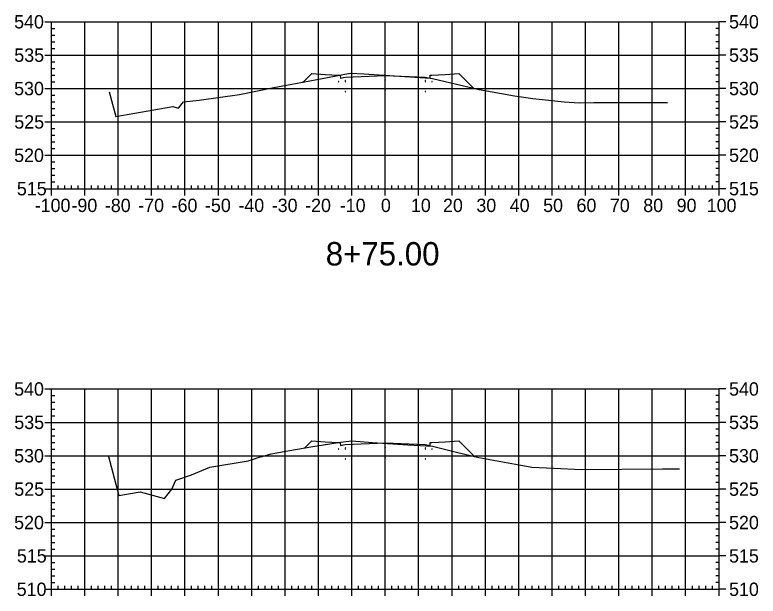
# Model space of a CAD drawing. Extents: x 708103 to 717568, y 374476 to 378707.
# Drawn here: x 716520.5 to 716743.2, y 376546 to 376720.1 of the extents above; entities that cross this region are included whole.
import ezdxf

# ---------------------------------------------------------------- set-up
doc = ezdxf.new("R2010")
doc.units = 0
for name, color, linetype in [('1', 7, 'Continuous'), ('14', 7, 'Continuous'), ('22', 7, 'Continuous'), ('57', 7, 'Continuous'), ('Existing', 7, 'Continuous')]:
    doc.layers.add(name, color=color, linetype=linetype)

msp = doc.modelspace()

# ---------------------------------------------------------------- linework, layer by layer
for points in [[(716617.45, 376700.07), (716617.55, 376700.07), (716617.55, 376700.17), (716617.45, 376700.17)], [(716619.45, 376700.4), (716619.55, 376700.4), (716619.55, 376700.5), (716619.45, 376700.5)], [(716619.45, 376700.07), (716619.55, 376700.07), (716619.55, 376700.17), (716619.45, 376700.17)], [(716631.45, 376700.55), (716631.55, 376700.55), (716631.55, 376700.65), (716631.45, 376700.65)], [(716643.45, 376700.4), (716643.55, 376700.4), (716643.55, 376700.5), (716643.45, 376700.5)], [(716643.45, 376700.07), (716643.55, 376700.07), (716643.55, 376700.17), (716643.45, 376700.17)], [(716645.45, 376700.07), (716645.55, 376700.07), (716645.55, 376700.17), (716645.45, 376700.17)], [(716619.45, 376697.07), (716619.55, 376697.07), (716619.55, 376697.17), (716619.45, 376697.17)], [(716631.45, 376697.55), (716631.55, 376697.55), (716631.55, 376697.65), (716631.45, 376697.65)], [(716643.45, 376697.07), (716643.55, 376697.07), (716643.55, 376697.17), (716643.45, 376697.17)], [(716617.45, 376590.02), (716617.55, 376590.02), (716617.55, 376590.12), (716617.45, 376590.12)], [(716619.45, 376590.36), (716619.55, 376590.36), (716619.55, 376590.46), (716619.45, 376590.46)], [(716619.45, 376590.02), (716619.55, 376590.02), (716619.55, 376590.12), (716619.45, 376590.12)], [(716631.45, 376590.5), (716631.55, 376590.5), (716631.55, 376590.6), (716631.45, 376590.6)], [(716643.45, 376590.36), (716643.55, 376590.36), (716643.55, 376590.46), (716643.45, 376590.46)], [(716643.45, 376590.02), (716643.55, 376590.02), (716643.55, 376590.12), (716643.45, 376590.12)], [(716645.45, 376590.02), (716645.55, 376590.02), (716645.55, 376590.12), (716645.45, 376590.12)], [(716631.45, 376587.5), (716631.55, 376587.5), (716631.55, 376587.6), (716631.45, 376587.6)], [(716619.45, 376587.02), (716619.55, 376587.02), (716619.55, 376587.12), (716619.45, 376587.12)], [(716643.45, 376587.02), (716643.55, 376587.02), (716643.55, 376587.12), (716643.45, 376587.12)]]:
    msp.add_lwpolyline(points, close=True)
at = {"layer": '14'}
for points in [[(716606.91, 376700.01), (716606.91, 376700.06), (716606.91, 376700.01), (716606.86, 376700.01), (716606.91, 376700.01), (716606.91, 376699.96), (716606.91, 376700.01), (716606.96, 376700.01)], [(716657.93, 376698.16), (716657.93, 376698.21), (716657.93, 376698.16), (716657.88, 376698.16), (716657.93, 376698.16), (716657.93, 376698.11), (716657.93, 376698.16), (716657.98, 376698.16)], [(716607.37, 376590.42), (716607.37, 376590.47), (716607.37, 376590.42), (716607.32, 376590.42), (716607.37, 376590.42), (716607.37, 376590.37), (716607.37, 376590.42), (716607.42, 376590.42)], [(716658.21, 376587.84), (716658.21, 376587.89), (716658.21, 376587.84), (716658.16, 376587.84), (716658.21, 376587.84), (716658.21, 376587.79), (716658.21, 376587.84), (716658.26, 376587.84)]]:
    msp.add_lwpolyline(points, dxfattribs=at)
at = {"layer": '22'}
for points in [[(716606.91, 376700.01), (716609.5, 376702.6), (716613.5, 376702.28), (716617.5, 376702.12), (716618, 376702.12), (716618.08, 376701.2), (716619.5, 376701.45), (716631.5, 376701.93), (716643.5, 376701.45), (716644.91, 376701.2), (716645, 376702.12), (716645.5, 376702.12), (716649.5, 376702.28), (716653.5, 376702.6), (716657.93, 376698.16)], [(716607.37, 376590.42), (716609.5, 376592.55), (716613.5, 376592.23), (716617.5, 376592.07), (716618, 376592.07), (716618.08, 376591.16), (716619.5, 376591.41), (716631.5, 376591.89), (716643.5, 376591.41), (716644.91, 376591.16), (716645, 376592.07), (716645.5, 376592.07), (716649.5, 376592.23), (716653.5, 376592.55), (716658.21, 376587.84)]]:
    msp.add_lwpolyline(points, dxfattribs=at)
at = {"layer": '57'}
for p, q in [((716529.5, 376718.07), (716531.5, 376718.07)), ((716531.5, 376718.07), (716731.5, 376718.07)), ((716531.5, 376668.07), (716531.5, 376718.07)), ((716531.5, 376668.07), (716531.5, 376718.07)), ((716541.5, 376668.07), (716541.5, 376718.07)), ((716551.5, 376668.07), (716551.5, 376718.07)), ((716561.5, 376668.07), (716561.5, 376718.07)), ((716571.5, 376668.07), (716571.5, 376718.07)), ((716581.5, 376668.07), (716581.5, 376718.07)), ((716591.5, 376668.07), (716591.5, 376718.07)), ((716601.5, 376668.07), (716601.5, 376718.07)), ((716611.5, 376668.07), (716611.5, 376718.07)), ((716621.5, 376668.07), (716621.5, 376718.07)), ((716631.5, 376668.07), (716631.5, 376718.07)), ((716641.5, 376668.07), (716641.5, 376718.07)), ((716651.5, 376668.07), (716651.5, 376718.07)), ((716661.5, 376668.07), (716661.5, 376718.07)), ((716671.5, 376668.07), (716671.5, 376718.07)), ((716681.5, 376668.07), (716681.5, 376718.07)), ((716691.5, 376668.07), (716691.5, 376718.07)), ((716701.5, 376668.07), (716701.5, 376718.07)), ((716711.5, 376668.07), (716711.5, 376718.07)), ((716721.5, 376668.07), (716721.5, 376718.07)), ((716731.5, 376668.07), (716731.5, 376718.07)), ((716731.5, 376668.07), (716731.5, 376718.07)), ((716733.5, 376718.07), (716731.5, 376718.07)), ((716531.5, 376716.07), (716532.5, 376716.07)), ((716731.5, 376716.07), (716730.5, 376716.07)), ((716531.5, 376714.07), (716532.5, 376714.07)), ((716731.5, 376714.07), (716730.5, 376714.07)), ((716531.5, 376712.07), (716532.5, 376712.07)), ((716531.5, 376710.07), (716532.5, 376710.07)), ((716731.5, 376712.07), (716730.5, 376712.07)), ((716731.5, 376710.07), (716730.5, 376710.07)), ((716529.5, 376708.07), (716531.5, 376708.07)), ((716531.5, 376708.07), (716731.5, 376708.07)), ((716733.5, 376708.07), (716731.5, 376708.07)), ((716531.5, 376706.07), (716532.5, 376706.07)), ((716731.5, 376706.07), (716730.5, 376706.07)), ((716531.5, 376704.07), (716532.5, 376704.07)), ((716731.5, 376704.07), (716730.5, 376704.07)), ((716531.5, 376702.07), (716532.5, 376702.07)), ((716731.5, 376702.07), (716730.5, 376702.07)), ((716531.5, 376700.07), (716532.5, 376700.07)), ((716731.5, 376700.07), (716730.5, 376700.07)), ((716529.5, 376698.07), (716531.5, 376698.07)), ((716531.5, 376698.07), (716731.5, 376698.07)), ((716733.5, 376698.07), (716731.5, 376698.07)), ((716531.5, 376696.07), (716532.5, 376696.07)), ((716731.5, 376696.07), (716730.5, 376696.07)), ((716531.5, 376694.07), (716532.5, 376694.07)), ((716731.5, 376694.07), (716730.5, 376694.07)), ((716531.5, 376692.07), (716532.5, 376692.07)), ((716531.5, 376690.07), (716532.5, 376690.07)), ((716731.5, 376692.07), (716730.5, 376692.07)), ((716731.5, 376690.07), (716730.5, 376690.07)), ((716529.5, 376688.07), (716531.5, 376688.07)), ((716531.5, 376688.07), (716731.5, 376688.07)), ((716733.5, 376688.07), (716731.5, 376688.07)), ((716531.5, 376686.07), (716532.5, 376686.07)), ((716731.5, 376686.07), (716730.5, 376686.07)), ((716531.5, 376684.07), (716532.5, 376684.07)), ((716731.5, 376684.07), (716730.5, 376684.07)), ((716531.5, 376682.07), (716532.5, 376682.07)), ((716731.5, 376682.07), (716730.5, 376682.07)), ((716531.5, 376680.07), (716532.5, 376680.07)), ((716731.5, 376680.07), (716730.5, 376680.07)), ((716529.5, 376678.07), (716531.5, 376678.07)), ((716531.5, 376678.07), (716731.5, 376678.07)), ((716733.5, 376678.07), (716731.5, 376678.07)), ((716531.5, 376676.07), (716532.5, 376676.07)), ((716731.5, 376676.07), (716730.5, 376676.07)), ((716531.5, 376674.07), (716532.5, 376674.07)), ((716731.5, 376674.07), (716730.5, 376674.07)), ((716531.5, 376672.07), (716532.5, 376672.07)), ((716531.5, 376670.07), (716532.5, 376670.07)), ((716731.5, 376672.07), (716730.5, 376672.07)), ((716731.5, 376670.07), (716730.5, 376670.07)), ((716529.5, 376668.07), (716531.5, 376668.07)), ((716531.5, 376668.07), (716731.5, 376668.07)), ((716531.5, 376668.07), (716731.5, 376668.07)), ((716531.5, 376666.07), (716531.5, 376668.07)), ((716533.5, 376668.07), (716533.5, 376669.07)), ((716535.5, 376668.07), (716535.5, 376669.07)), ((716537.5, 376668.07), (716537.5, 376669.07)), ((716539.5, 376668.07), (716539.5, 376669.07)), ((716541.5, 376666.07), (716541.5, 376668.07)), ((716543.5, 376668.07), (716543.5, 376669.07)), ((716545.5, 376668.07), (716545.5, 376669.07)), ((716547.5, 376668.07), (716547.5, 376669.07)), ((716549.5, 376668.07), (716549.5, 376669.07)), ((716551.5, 376666.07), (716551.5, 376668.07)), ((716553.5, 376668.07), (716553.5, 376669.07)), ((716555.5, 376668.07), (716555.5, 376669.07)), ((716557.5, 376668.07), (716557.5, 376669.07)), ((716559.5, 376668.07), (716559.5, 376669.07)), ((716561.5, 376666.07), (716561.5, 376668.07)), ((716563.5, 376668.07), (716563.5, 376669.07)), ((716565.5, 376668.07), (716565.5, 376669.07)), ((716567.5, 376668.07), (716567.5, 376669.07)), ((716569.5, 376668.07), (716569.5, 376669.07)), ((716571.5, 376666.07), (716571.5, 376668.07)), ((716573.5, 376668.07), (716573.5, 376669.07)), ((716575.5, 376668.07), (716575.5, 376669.07)), ((716577.5, 376668.07), (716577.5, 376669.07)), ((716579.5, 376668.07), (716579.5, 376669.07)), ((716581.5, 376666.07), (716581.5, 376668.07)), ((716583.5, 376668.07), (716583.5, 376669.07)), ((716585.5, 376668.07), (716585.5, 376669.07)), ((716587.5, 376668.07), (716587.5, 376669.07)), ((716589.5, 376668.07), (716589.5, 376669.07)), ((716591.5, 376666.07), (716591.5, 376668.07)), ((716593.5, 376668.07), (716593.5, 376669.07)), ((716595.5, 376668.07), (716595.5, 376669.07)), ((716597.5, 376668.07), (716597.5, 376669.07)), ((716599.5, 376668.07), (716599.5, 376669.07)), ((716601.5, 376666.07), (716601.5, 376668.07)), ((716603.5, 376668.07), (716603.5, 376669.07)), ((716605.5, 376668.07), (716605.5, 376669.07)), ((716607.5, 376668.07), (716607.5, 376669.07)), ((716609.5, 376668.07), (716609.5, 376669.07)), ((716611.5, 376666.07), (716611.5, 376668.07)), ((716613.5, 376668.07), (716613.5, 376669.07)), ((716615.5, 376668.07), (716615.5, 376669.07)), ((716617.5, 376668.07), (716617.5, 376669.07)), ((716619.5, 376668.07), (716619.5, 376669.07)), ((716621.5, 376666.07), (716621.5, 376668.07)), ((716623.5, 376668.07), (716623.5, 376669.07)), ((716625.5, 376668.07), (716625.5, 376669.07)), ((716627.5, 376668.07), (716627.5, 376669.07)), ((716629.5, 376668.07), (716629.5, 376669.07)), ((716631.5, 376666.07), (716631.5, 376668.07)), ((716633.5, 376668.07), (716633.5, 376669.07)), ((716635.5, 376668.07), (716635.5, 376669.07)), ((716637.5, 376668.07), (716637.5, 376669.07)), ((716639.5, 376668.07), (716639.5, 376669.07)), ((716641.5, 376666.07), (716641.5, 376668.07)), ((716643.5, 376668.07), (716643.5, 376669.07)), ((716645.5, 376668.07), (716645.5, 376669.07)), ((716647.5, 376668.07), (716647.5, 376669.07)), ((716649.5, 376668.07), (716649.5, 376669.07)), ((716651.5, 376666.07), (716651.5, 376668.07)), ((716653.5, 376668.07), (716653.5, 376669.07)), ((716655.5, 376668.07), (716655.5, 376669.07)), ((716657.5, 376668.07), (716657.5, 376669.07)), ((716659.5, 376668.07), (716659.5, 376669.07)), ((716661.5, 376666.07), (716661.5, 376668.07)), ((716663.5, 376668.07), (716663.5, 376669.07)), ((716665.5, 376668.07), (716665.5, 376669.07)), ((716667.5, 376668.07), (716667.5, 376669.07)), ((716669.5, 376668.07), (716669.5, 376669.07)), ((716671.5, 376666.07), (716671.5, 376668.07)), ((716673.5, 376668.07), (716673.5, 376669.07)), ((716675.5, 376668.07), (716675.5, 376669.07)), ((716677.5, 376668.07), (716677.5, 376669.07)), ((716679.5, 376668.07), (716679.5, 376669.07)), ((716681.5, 376666.07), (716681.5, 376668.07)), ((716683.5, 376668.07), (716683.5, 376669.07)), ((716685.5, 376668.07), (716685.5, 376669.07)), ((716687.5, 376668.07), (716687.5, 376669.07)), ((716689.5, 376668.07), (716689.5, 376669.07)), ((716691.5, 376666.07), (716691.5, 376668.07)), ((716693.5, 376668.07), (716693.5, 376669.07)), ((716695.5, 376668.07), (716695.5, 376669.07)), ((716697.5, 376668.07), (716697.5, 376669.07)), ((716699.5, 376668.07), (716699.5, 376669.07)), ((716701.5, 376666.07), (716701.5, 376668.07)), ((716703.5, 376668.07), (716703.5, 376669.07)), ((716705.5, 376668.07), (716705.5, 376669.07)), ((716707.5, 376668.07), (716707.5, 376669.07)), ((716709.5, 376668.07), (716709.5, 376669.07)), ((716711.5, 376666.07), (716711.5, 376668.07)), ((716713.5, 376668.07), (716713.5, 376669.07)), ((716715.5, 376668.07), (716715.5, 376669.07)), ((716717.5, 376668.07), (716717.5, 376669.07)), ((716719.5, 376668.07), (716719.5, 376669.07)), ((716721.5, 376666.07), (716721.5, 376668.07)), ((716723.5, 376668.07), (716723.5, 376669.07)), ((716725.5, 376668.07), (716725.5, 376669.07)), ((716727.5, 376668.07), (716727.5, 376669.07)), ((716729.5, 376668.07), (716729.5, 376669.07)), ((716731.5, 376666.07), (716731.5, 376668.07)), ((716733.5, 376668.07), (716731.5, 376668.07)), ((716529.5, 376608.07), (716531.5, 376608.07)), ((716531.5, 376608.07), (716731.5, 376608.07)), ((716531.5, 376548.07), (716531.5, 376608.07)), ((716531.5, 376548.07), (716531.5, 376608.07)), ((716541.5, 376548.07), (716541.5, 376608.07)), ((716551.5, 376548.07), (716551.5, 376608.07)), ((716561.5, 376548.07), (716561.5, 376608.07)), ((716571.5, 376548.07), (716571.5, 376608.07)), ((716581.5, 376548.07), (716581.5, 376608.07)), ((716591.5, 376548.07), (716591.5, 376608.07)), ((716601.5, 376548.07), (716601.5, 376608.07)), ((716611.5, 376548.07), (716611.5, 376608.07)), ((716621.5, 376548.07), (716621.5, 376608.07)), ((716631.5, 376548.07), (716631.5, 376608.07)), ((716641.5, 376548.07), (716641.5, 376608.07)), ((716651.5, 376548.07), (716651.5, 376608.07)), ((716661.5, 376548.07), (716661.5, 376608.07)), ((716671.5, 376548.07), (716671.5, 376608.07)), ((716681.5, 376548.07), (716681.5, 376608.07)), ((716691.5, 376548.07), (716691.5, 376608.07)), ((716701.5, 376548.07), (716701.5, 376608.07)), ((716711.5, 376548.07), (716711.5, 376608.07)), ((716721.5, 376548.07), (716721.5, 376608.07)), ((716731.5, 376548.07), (716731.5, 376608.07)), ((716731.5, 376548.07), (716731.5, 376608.07)), ((716733.5, 376608.07), (716731.5, 376608.07)), ((716531.5, 376606.07), (716532.5, 376606.07)), ((716731.5, 376606.07), (716730.5, 376606.07)), ((716531.5, 376604.07), (716532.5, 376604.07)), ((716731.5, 376604.07), (716730.5, 376604.07)), ((716531.5, 376602.07), (716532.5, 376602.07)), ((716731.5, 376602.07), (716730.5, 376602.07)), ((716531.5, 376600.07), (716532.5, 376600.07)), ((716731.5, 376600.07), (716730.5, 376600.07)), ((716529.5, 376598.07), (716531.5, 376598.07)), ((716531.5, 376598.07), (716731.5, 376598.07)), ((716733.5, 376598.07), (716731.5, 376598.07)), ((716531.5, 376596.07), (716532.5, 376596.07)), ((716731.5, 376596.07), (716730.5, 376596.07)), ((716531.5, 376594.07), (716532.5, 376594.07)), ((716531.5, 376592.07), (716532.5, 376592.07)), ((716731.5, 376594.07), (716730.5, 376594.07)), ((716731.5, 376592.07), (716730.5, 376592.07)), ((716531.5, 376590.07), (716532.5, 376590.07)), ((716731.5, 376590.07), (716730.5, 376590.07)), ((716529.5, 376588.07), (716531.5, 376588.07)), ((716531.5, 376588.07), (716731.5, 376588.07)), ((716733.5, 376588.07), (716731.5, 376588.07)), ((716531.5, 376586.07), (716532.5, 376586.07)), ((716731.5, 376586.07), (716730.5, 376586.07)), ((716531.5, 376584.07), (716532.5, 376584.07)), ((716731.5, 376584.07), (716730.5, 376584.07)), ((716531.5, 376582.07), (716532.5, 376582.07)), ((716731.5, 376582.07), (716730.5, 376582.07)), ((716531.5, 376580.07), (716532.5, 376580.07)), ((716731.5, 376580.07), (716730.5, 376580.07)), ((716529.5, 376578.07), (716531.5, 376578.07)), ((716531.5, 376578.07), (716731.5, 376578.07)), ((716733.5, 376578.07), (716731.5, 376578.07)), ((716531.5, 376576.07), (716532.5, 376576.07)), ((716731.5, 376576.07), (716730.5, 376576.07)), ((716531.5, 376574.07), (716532.5, 376574.07)), ((716531.5, 376572.07), (716532.5, 376572.07)), ((716731.5, 376574.07), (716730.5, 376574.07)), ((716731.5, 376572.07), (716730.5, 376572.07)), ((716531.5, 376570.07), (716532.5, 376570.07)), ((716731.5, 376570.07), (716730.5, 376570.07)), ((716529.5, 376568.07), (716531.5, 376568.07)), ((716531.5, 376568.07), (716731.5, 376568.07)), ((716733.5, 376568.07), (716731.5, 376568.07)), ((716531.5, 376566.07), (716532.5, 376566.07)), ((716731.5, 376566.07), (716730.5, 376566.07)), ((716531.5, 376564.07), (716532.5, 376564.07)), ((716731.5, 376564.07), (716730.5, 376564.07)), ((716531.5, 376562.07), (716532.5, 376562.07)), ((716731.5, 376562.07), (716730.5, 376562.07)), ((716531.5, 376560.07), (716532.5, 376560.07)), ((716731.5, 376560.07), (716730.5, 376560.07)), ((716529.5, 376558.07), (716531.5, 376558.07)), ((716531.5, 376558.07), (716731.5, 376558.07)), ((716733.5, 376558.07), (716731.5, 376558.07)), ((716531.5, 376556.07), (716532.5, 376556.07)), ((716731.5, 376556.07), (716730.5, 376556.07)), ((716531.5, 376554.07), (716532.5, 376554.07)), ((716531.5, 376552.07), (716532.5, 376552.07)), ((716731.5, 376554.07), (716730.5, 376554.07)), ((716731.5, 376552.07), (716730.5, 376552.07)), ((716531.5, 376550.07), (716532.5, 376550.07)), ((716731.5, 376550.07), (716730.5, 376550.07)), ((716529.5, 376548.07), (716531.5, 376548.07)), ((716531.5, 376548.07), (716731.5, 376548.07)), ((716531.5, 376548.07), (716731.5, 376548.07)), ((716531.5, 376546.07), (716531.5, 376548.07)), ((716533.5, 376548.07), (716533.5, 376549.07)), ((716535.5, 376548.07), (716535.5, 376549.07)), ((716537.5, 376548.07), (716537.5, 376549.07)), ((716539.5, 376548.07), (716539.5, 376549.07)), ((716541.5, 376546.07), (716541.5, 376548.07)), ((716543.5, 376548.07), (716543.5, 376549.07)), ((716545.5, 376548.07), (716545.5, 376549.07)), ((716547.5, 376548.07), (716547.5, 376549.07)), ((716549.5, 376548.07), (716549.5, 376549.07)), ((716551.5, 376546.07), (716551.5, 376548.07)), ((716553.5, 376548.07), (716553.5, 376549.07)), ((716555.5, 376548.07), (716555.5, 376549.07)), ((716557.5, 376548.07), (716557.5, 376549.07)), ((716559.5, 376548.07), (716559.5, 376549.07)), ((716561.5, 376546.07), (716561.5, 376548.07)), ((716563.5, 376548.07), (716563.5, 376549.07)), ((716565.5, 376548.07), (716565.5, 376549.07)), ((716567.5, 376548.07), (716567.5, 376549.07)), ((716569.5, 376548.07), (716569.5, 376549.07)), ((716571.5, 376546.07), (716571.5, 376548.07)), ((716573.5, 376548.07), (716573.5, 376549.07)), ((716575.5, 376548.07), (716575.5, 376549.07)), ((716577.5, 376548.07), (716577.5, 376549.07)), ((716579.5, 376548.07), (716579.5, 376549.07)), ((716581.5, 376546.07), (716581.5, 376548.07)), ((716583.5, 376548.07), (716583.5, 376549.07)), ((716585.5, 376548.07), (716585.5, 376549.07)), ((716587.5, 376548.07), (716587.5, 376549.07)), ((716589.5, 376548.07), (716589.5, 376549.07)), ((716591.5, 376546.07), (716591.5, 376548.07)), ((716593.5, 376548.07), (716593.5, 376549.07)), ((716595.5, 376548.07), (716595.5, 376549.07)), ((716597.5, 376548.07), (716597.5, 376549.07)), ((716599.5, 376548.07), (716599.5, 376549.07)), ((716601.5, 376546.07), (716601.5, 376548.07)), ((716603.5, 376548.07), (716603.5, 376549.07)), ((716605.5, 376548.07), (716605.5, 376549.07)), ((716607.5, 376548.07), (716607.5, 376549.07)), ((716609.5, 376548.07), (716609.5, 376549.07)), ((716611.5, 376546.07), (716611.5, 376548.07)), ((716613.5, 376548.07), (716613.5, 376549.07)), ((716615.5, 376548.07), (716615.5, 376549.07)), ((716617.5, 376548.07), (716617.5, 376549.07)), ((716619.5, 376548.07), (716619.5, 376549.07)), ((716621.5, 376546.07), (716621.5, 376548.07)), ((716623.5, 376548.07), (716623.5, 376549.07)), ((716625.5, 376548.07), (716625.5, 376549.07)), ((716627.5, 376548.07), (716627.5, 376549.07)), ((716629.5, 376548.07), (716629.5, 376549.07)), ((716631.5, 376546.07), (716631.5, 376548.07)), ((716633.5, 376548.07), (716633.5, 376549.07)), ((716635.5, 376548.07), (716635.5, 376549.07)), ((716637.5, 376548.07), (716637.5, 376549.07)), ((716639.5, 376548.07), (716639.5, 376549.07)), ((716641.5, 376546.07), (716641.5, 376548.07)), ((716643.5, 376548.07), (716643.5, 376549.07)), ((716645.5, 376548.07), (716645.5, 376549.07)), ((716647.5, 376548.07), (716647.5, 376549.07)), ((716649.5, 376548.07), (716649.5, 376549.07)), ((716651.5, 376546.07), (716651.5, 376548.07)), ((716653.5, 376548.07), (716653.5, 376549.07)), ((716655.5, 376548.07), (716655.5, 376549.07)), ((716657.5, 376548.07), (716657.5, 376549.07)), ((716659.5, 376548.07), (716659.5, 376549.07)), ((716661.5, 376546.07), (716661.5, 376548.07)), ((716663.5, 376548.07), (716663.5, 376549.07)), ((716665.5, 376548.07), (716665.5, 376549.07)), ((716667.5, 376548.07), (716667.5, 376549.07)), ((716669.5, 376548.07), (716669.5, 376549.07)), ((716671.5, 376546.07), (716671.5, 376548.07)), ((716673.5, 376548.07), (716673.5, 376549.07)), ((716675.5, 376548.07), (716675.5, 376549.07)), ((716677.5, 376548.07), (716677.5, 376549.07)), ((716679.5, 376548.07), (716679.5, 376549.07)), ((716681.5, 376546.07), (716681.5, 376548.07)), ((716683.5, 376548.07), (716683.5, 376549.07)), ((716685.5, 376548.07), (716685.5, 376549.07)), ((716687.5, 376548.07), (716687.5, 376549.07)), ((716689.5, 376548.07), (716689.5, 376549.07)), ((716691.5, 376546.07), (716691.5, 376548.07)), ((716693.5, 376548.07), (716693.5, 376549.07)), ((716695.5, 376548.07), (716695.5, 376549.07)), ((716697.5, 376548.07), (716697.5, 376549.07)), ((716699.5, 376548.07), (716699.5, 376549.07)), ((716701.5, 376546.07), (716701.5, 376548.07)), ((716703.5, 376548.07), (716703.5, 376549.07)), ((716705.5, 376548.07), (716705.5, 376549.07)), ((716707.5, 376548.07), (716707.5, 376549.07)), ((716709.5, 376548.07), (716709.5, 376549.07)), ((716711.5, 376546.07), (716711.5, 376548.07)), ((716713.5, 376548.07), (716713.5, 376549.07)), ((716715.5, 376548.07), (716715.5, 376549.07)), ((716717.5, 376548.07), (716717.5, 376549.07)), ((716719.5, 376548.07), (716719.5, 376549.07)), ((716721.5, 376546.07), (716721.5, 376548.07)), ((716723.5, 376548.07), (716723.5, 376549.07)), ((716725.5, 376548.07), (716725.5, 376549.07)), ((716727.5, 376548.07), (716727.5, 376549.07)), ((716729.5, 376548.07), (716729.5, 376549.07)), ((716731.5, 376546.07), (716731.5, 376548.07)), ((716733.5, 376548.07), (716731.5, 376548.07))]:
    msp.add_line(p, q, dxfattribs=at)
at = {"layer": 'Existing'}
for points in [[(716548.84, 376697.06), (716550.78, 376689.74), (716567.86, 376692.67), (716569.55, 376692.18), (716571.08, 376694.11), (716575.73, 376694.61), (716587.82, 376696.26), (716598.14, 376698.33), (716610.05, 376700.61), (716620.96, 376702.66), (716625.11, 376702.47), (716643.47, 376701.32), (716645.05, 376701.22), (716645.66, 376701.08), (716659.59, 376697.77), (716670.18, 376695.88), (716675.7, 376695.11), (716685.15, 376694.08), (716689.55, 376693.83), (716693.97, 376693.87), (716716.03, 376693.9)], [(716548.64, 376587.85), (716551.73, 376576.17), (716558.06, 376577.29), (716565.37, 376575.24), (716567.59, 376578.05), (716568.74, 376580.72), (716573.43, 376582.38), (716578.97, 376584.67), (716590.43, 376586.56), (716591.7, 376586.96), (716593.76, 376587.61), (716594.67, 376587.87), (716597.34, 376588.62), (716597.96, 376588.72), (716599.48, 376589), (716602.35, 376589.51), (716609.76, 376590.85), (716618.14, 376592.15), (716621.53, 376592.53), (716627.71, 376592.05), (716638.23, 376591.36), (716645.66, 376590.91), (716652.87, 376589.12), (716659.54, 376587.52), (716670.56, 376585.55), (716675.39, 376584.6), (716682, 376584.39), (716690.32, 376583.93), (716714.58, 376584.11), (716719.68, 376584.11)]]:
    msp.add_lwpolyline(points, dxfattribs=at)

# ---------------------------------------------------------------- texts
at = {"layer": '1'}
msp.add_text('8+75.00', height=7, dxfattribs=at).set_placement((716613.67, 376645.07))
at = {"layer": '14'}
for p in [(716613.46, 376702.23), (716613.46, 376701.56), (716617.46, 376701.4), (716645.46, 376701.4), (716649.46, 376702.23), (716649.46, 376701.56), (716613.46, 376592.18), (716649.46, 376592.18), (716613.46, 376591.52), (716617.46, 376591.36), (716645.46, 376591.36), (716649.46, 376591.52)]:
    msp.add_text('+', height=0.1, dxfattribs=at).set_placement(p)
at = {"layer": '57'}
for s, p in [('540', (716520.32, 376716.07)), ('540', (716734.5, 376716.07)), ('535', (716520.37, 376706.07)), ('535', (716734.5, 376706.07)), ('530', (716520.32, 376696.07)), ('530', (716734.5, 376696.07)), ('525', (716520.37, 376686.07)), ('525', (716734.5, 376686.07)), ('520', (716520.32, 376676.07)), ('520', (716734.5, 376676.07)), ('515', (716521.14, 376666.07)), ('515', (716734.5, 376666.07)), ('-100', (716526.49, 376661.07)), ('-90', (716537.5, 376661.07)), ('-80', (716547.5, 376661.07)), ('-70', (716557.5, 376661.07)), ('-60', (716567.5, 376661.07)), ('-50', (716577.5, 376661.07)), ('-40', (716587.5, 376661.07)), ('-30', (716597.5, 376661.07)), ('-20', (716607.5, 376661.07)), ('-10', (716617.88, 376661.07)), ('0', (716630.2, 376661.07)), ('10', (716639.19, 376661.07)), ('20', (716648.8, 376661.07)), ('30', (716658.8, 376661.07)), ('40', (716668.8, 376661.07)), ('50', (716678.8, 376661.07)), ('60', (716688.8, 376661.07)), ('70', (716698.8, 376661.07)), ('80', (716708.8, 376661.07)), ('90', (716718.8, 376661.07)), ('100', (716727.8, 376661.07)), ('540', (716520.32, 376606.07)), ('540', (716734.5, 376606.07)), ('535', (716520.37, 376596.07)), ('535', (716734.5, 376596.07)), ('530', (716520.32, 376586.07)), ('530', (716734.5, 376586.07)), ('525', (716520.37, 376576.07)), ('525', (716734.5, 376576.07)), ('520', (716520.32, 376566.07)), ('520', (716734.5, 376566.07)), ('515', (716521.14, 376556.07)), ('515', (716734.5, 376556.07)), ('510', (716521.09, 376546.07)), ('510', (716734.5, 376546.07))]:
    msp.add_text(s, height=4, dxfattribs=at).set_placement(p)

doc.saveas('drawing.dxf')
